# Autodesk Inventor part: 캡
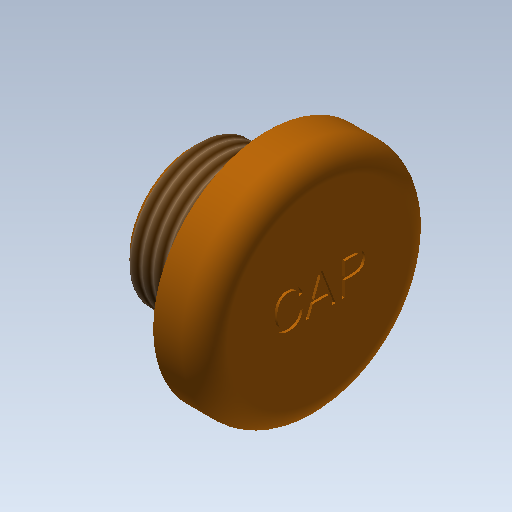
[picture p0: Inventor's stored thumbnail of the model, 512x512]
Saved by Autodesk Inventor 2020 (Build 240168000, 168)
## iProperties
Created: 2017-06
Part Number: 캡
Material: ABS 플라스틱
Document SubType Name: Modeling
Designer: mduedu
Density: 1 g/cm^3
Appearance: 주황색
Author: mduedu
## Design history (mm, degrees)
sketch "스케치1"
  geometry: L1 (0, 0)-(11, 0); L2 (11, 0)-(11, 10); L3 (11, 10)-(6.5, 10); L4 (0, 6)-(0, 0); L5 (0, 6)-(6, 6); L6 (6, 6)-(6, 9); L7 (6, 9)-(6.5, 9); L8 (6.5, 9)-(6.5, 10)
  constraints: 16 end point, 2 horizontal, 2 parallel, 2 perpendicular, 2 point on line, 1 vertical
  dimensions: "d0" = 20 diameter of L3 L1; "d2" = 12 diameter of L5 L1; "d6" = 5 distance between parallel lines of L2 L6; "d7" = 0.5 distance between parallel lines of L8 L6; "d8" = 18 diameter of L7 L1; "d9" = 6 distance between parallel lines of L6 L4
revolve "회전1" sketch "스케치1" stored, may be unused: angle "d10" = 90 deg
hole "구멍1" diameter "d22" = 8; stored, may be unused: countersink angle "d26" = 90 deg, drill point angle "d28" = 0 deg; dims "d23" = 6, "d24" = 4, "d25" = 2, "d27" = 5, "d32" = 10, "d33" = 10
chamfer "모따기1" distance "d13" = 0.5; stored, may be unused: second distance "d14" = 2, angle "d15" = 45 deg
fillet "모깎기3" dims "d29" = 1
fillet "모깎기1" dims "d16" = 0.1
fillet "모깎기2" dims "d17" = 2
sketch "스케치3"
  geometry: 2 further points
  constraints: 1 coincident, 1 other
feature "엠보싱1" sketch "스케치3" dims "d18" = 0.2, "d19" = 0
feature "스레드1" dims "d30" = 10, "d31" = 0
node "솔리드1"
